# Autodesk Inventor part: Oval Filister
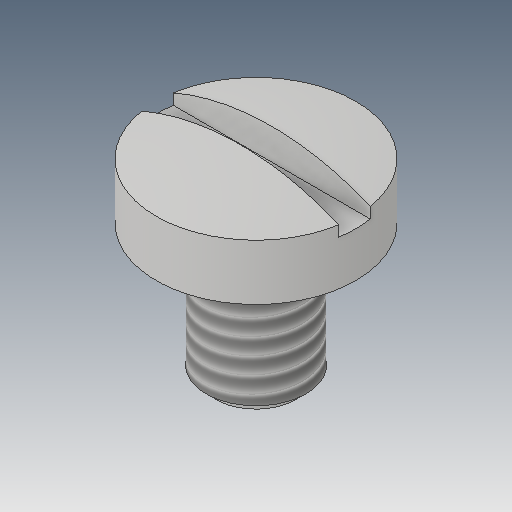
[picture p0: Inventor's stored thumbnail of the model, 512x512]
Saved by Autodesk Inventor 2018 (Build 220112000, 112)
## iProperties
Created: 2016-06
Part Number: Oval Filister
Material: Generic
Document SubType Name: Modeling
Designer: CADCIM
Density: 1 g/cm^3
Appearance: Default
Author: CADCIM
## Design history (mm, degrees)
sketch "Sketch1"
  geometry: 1 further point
sketch "Sketch2"
  geometry: C1 r 3 at (0, 0); 1 further point
  constraints: 1 centre point, 1 coincident
  dimensions: "d0" = 6 diameter of C1
extrude "Extrusion1" new body sketch "Sketch2" distance "d1" = 8; taper "d2" = 0 deg
sketch "Sketch3"
  geometry: 1 further point
sketch "Sketch4"
  geometry: L1 (8, 0)-(8, -6); L2 (8, -3)-(8, 3) reference; L3 (8, -6)-(11.35, -6); L4 (12.6, 0)-(8, 0); A1 r 15.025 centre (-2.425, 0) between (11.35, -6) and (12.6, 0); 2 further points
  constraints: 6 end point, 2 midpoint, 2 point on circle, 1 centre point, 1 horizontal, 1 horizontal alignment, 1 perpendicular, 1 point on line, 1 vertical
  dimensions: "d3" = 6 distance of L1.start L1.end; "d4" = 4.6 distance of L4.start L1.start; "d5" = 1.25 horizontal distance of L3.end L4.start
revolve "Revolution1" sketch "Sketch4" stored, may be unused: angle "d6" = 90 deg
workplane "Work Plane1"
sketch "Sketch5"
  geometry: L1 (6.611, -0.95)-(-6.611, -0.95); L2 (-6.611, -0.95)-(-6.611, 0.95); L3 (-6.611, 0.95)-(6.611, 0.95); L4 (6.611, 0.95)-(6.611, -0.95); L5 (6.611, 0)-(-6.611, 0); 2 further points
  constraints: 10 end point, 3 midpoint, 2 parallel, 1 coincident, 1 horizontal, 1 perpendicular
  dimensions: "d8" = 1.9 distance of L3.end L1.start
extrude "Extrusion2" cut sketch "Sketch5" distance "d9" = 1.9; taper "d10" = 0 deg
thread "Thread1" dims "d11" = 10, "d12" = 0
chamfer "Chamfer1" distance "d13" = 0.6; stored, may be unused: second distance "d14" = 2, angle "d15" = 45 deg
body "Solid1"
other parameters: "d7" = -4.6
